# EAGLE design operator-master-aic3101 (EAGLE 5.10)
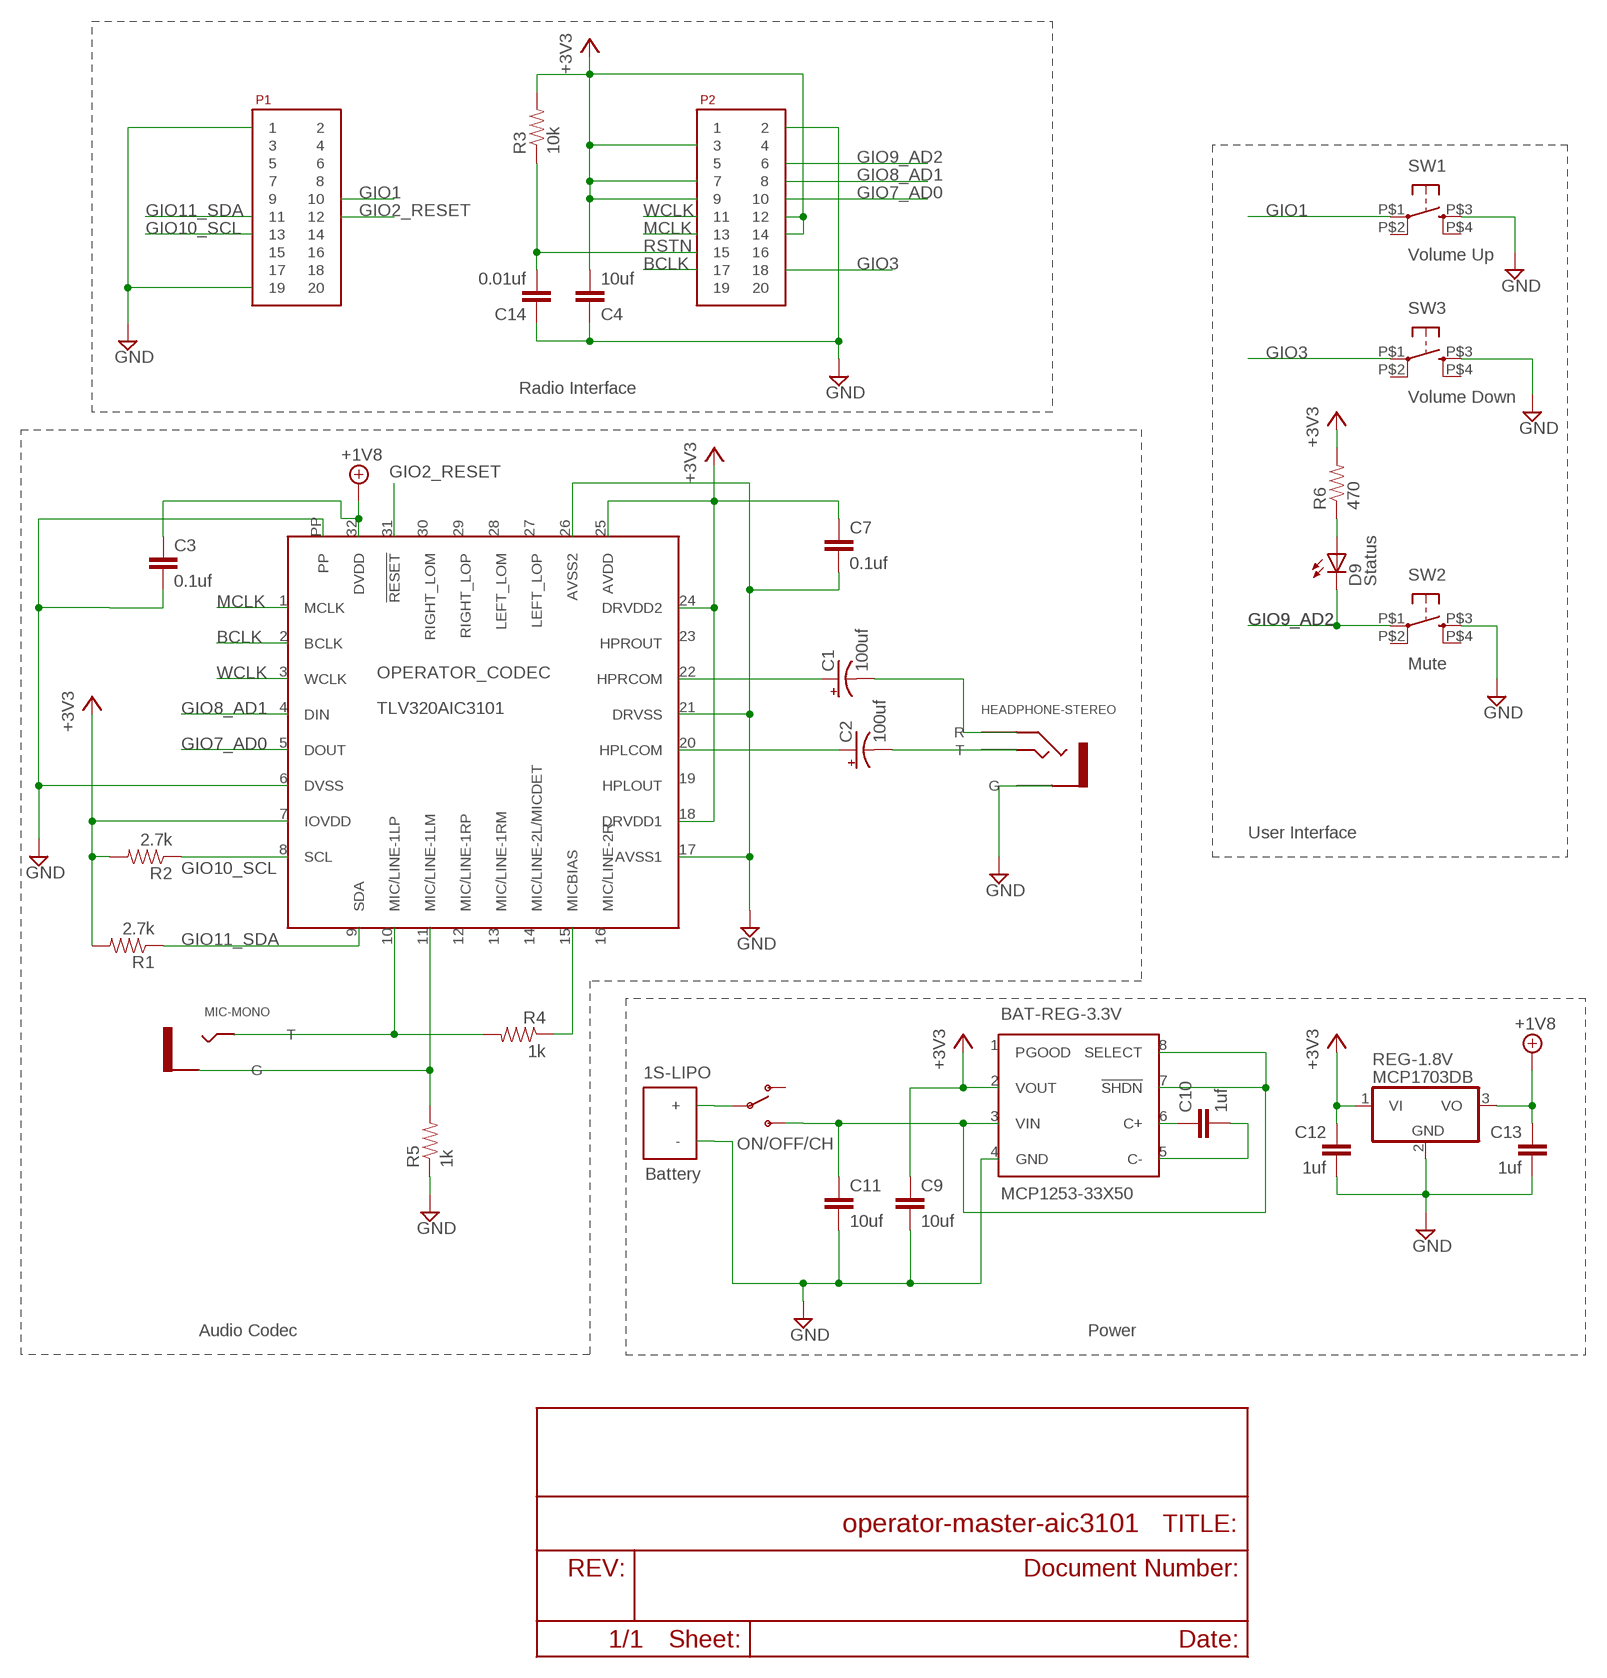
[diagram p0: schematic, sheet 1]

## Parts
1S-LIPO  Battery  JST-2MM-BAT-RIGHT-ANGLE  [JST-2MM-BAT-RIGHT-ANGLE]
BAT-REG-3.3V  MCP1253-33X50  [8MSOP]
C1  100uf  CPOL-USTT2D5  [TT2D5]
C2  100uf  CPOL-USTT2D5  [TT2D5]
C3  0.1uf  C-EUC1206  [C1206]
C4  10uf  C-EUC1206  [C1206]
C7  0.1uf  C-EUC1206  [C1206]
C9  10uf  C-EUC1206  [C1206]
C10  1uf  C-EUC1206  [C1206]
C11  10uf  C-EUC1206  [C1206]
C12  1uf  C-EUC1206  [C1206]
C13  1uf  C-EUC1206  [C1206]
C14  0.01uf  C-EUC1206  [C1206]
D9  Status  LEDCHIPLED_0805  [CHIPLED_0805]
HEADPHONE-STEREO  HEADPHONE-STEREO-NO-SWITCH  [HEADPHONE-STEREO-NO-SWITCH]
MIC-MONO  MIC-MONO  [MIC-MONO-SWITCH]
ON/OFF/CH  SWITCH-SPSTSMD2  [SWITCH-SPDT-SMD]
OPERATOR_CODEC  TLV320AIC3101  [SCHMARTBOARD-VQFN32-POWERPAD]
P1  SAMTEC-10X2  [SAMTEC-10X2]
P2  SAMTEC-10X2  [SAMTEC-10X2]
R1  2.7k  RESISTOR1206  [1206]
R2  2.7k  RESISTOR1206  [1206]
R3  10k  RESISTOR1206  [1206]
R4  1k  RESISTOR1206  [1206]
R5  1k  RESISTOR1206  [1206]
R6  470  RESISTOR1206  [1206]
REG-1.8V  MCP1703DB  [SOT223]
SW1  Volume Up  TAC_SWITCHKSA_SEALED  [KSA_SEALED_TAC_SWITCH]
SW2  Mute  TAC_SWITCHKSA_SEALED  [KSA_SEALED_TAC_SWITCH]
SW3  Volume Down  TAC_SWITCHKSA_SEALED  [KSA_SEALED_TAC_SWITCH]

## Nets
+3V3: BAT-REG-3.3V.2(VOUT) C4.2 C7.1 C9.1 C12.1 OPERATOR_CODEC.7(IOVDD) OPERATOR_CODEC.18(DRVDD1) OPERATOR_CODEC.24(DRVDD2) OPERATOR_CODEC.25(AVDD) P2.3 P2.7 P2.9 P2.12 P2.14 R1.2 R2.2 R3.2 R6.2 REG-1.8V.1(VI)
+18V: C3.1 C13.1 OPERATOR_CODEC.32(DVDD) REG-1.8V.3(VO) ; supply symbol labelled +1V8
BCLK: OPERATOR_CODEC.2(BCLK) P2.17
GIO1: P1.10 SW1.P$1
GIO2_RESET: OPERATOR_CODEC.31(!RESET) P1.12
GIO3: P2.18 SW3.P$1
GIO7_AD0: OPERATOR_CODEC.5(DOUT) P2.10
GIO8_AD1: OPERATOR_CODEC.4(DIN) P2.8
GIO9_AD2: D9.C P2.6 SW2.P$1
GIO10_SCL: OPERATOR_CODEC.8(SCL) P1.13 R2.1
GIO11_SDA: OPERATOR_CODEC.9(SDA) P1.11 R1.1
GND: 1S-LIPO.- BAT-REG-3.3V.4(GND) C3.2 C4.1 C7.2 C9.2 C11.2 C12.2 C13.2 C14.1 HEADPHONE-STEREO.G OPERATOR_CODEC.6(DVSS) OPERATOR_CODEC.17(AVSS1) OPERATOR_CODEC.21(DRVSS) OPERATOR_CODEC.26(AVSS2) OPERATOR_CODEC.PP P1.1 P1.19 P2.2 R5.1 REG-1.8V.2(GND) SW1.P$3 SW2.P$3 SW3.P$3
MCLK: OPERATOR_CODEC.1(MCLK) P2.13
N$1: MIC-MONO.G OPERATOR_CODEC.11(MIC/LINE-1LM) R5.2
N$2: 1S-LIPO.+ ON/OFF/CH.2(P)
N$3: MIC-MONO.T OPERATOR_CODEC.10(MIC/LINE-1LP) R4.2
N$4: OPERATOR_CODEC.15(MICBIAS) R4.1
N$5: C1.+ OPERATOR_CODEC.22(HPRCOM)
N$6: C2.+ OPERATOR_CODEC.20(HPLCOM)
N$7: C2.- HEADPHONE-STEREO.T
N$8: C1.- HEADPHONE-STEREO.R
N$10: D9.A R6.1
N$11: BAT-REG-3.3V.6(C+) C10.1
N$12: BAT-REG-3.3V.5(C-) C10.2
N$14: BAT-REG-3.3V.3(VIN) BAT-REG-3.3V.7(!SHDN) BAT-REG-3.3V.8(SELECT) C11.1 ON/OFF/CH.3(S)
RSTN: C14.2 P2.15 R3.1
WCLK: OPERATOR_CODEC.3(WCLK) P2.11
Unconnected: BAT-REG-3.3V.1(PGOOD) ON/OFF/CH.1(O) OPERATOR_CODEC.12(MIC/LINE-1RP) OPERATOR_CODEC.13(MIC/LINE-1RM) OPERATOR_CODEC.14(MIC/LINE-2L/MICDET) OPERATOR_CODEC.16(MIC/LINE-2R) OPERATOR_CODEC.19(HPLOUT) OPERATOR_CODEC.23(HPROUT) OPERATOR_CODEC.27(LEFT_LOP) OPERATOR_CODEC.28(LEFT_LOM) OPERATOR_CODEC.29(RIGHT_LOP) OPERATOR_CODEC.30(RIGHT_LOM) P1.2 P1.3 P1.4 P1.5 P1.6 P1.7 P1.8 P1.9 P1.14 P1.15 P1.16 P1.17 P1.18 P1.20 P2.1 P2.4 P2.5 P2.16 P2.19 P2.20 SW1.P$2 SW1.P$4 SW2.P$2 SW2.P$4 SW3.P$2 SW3.P$4

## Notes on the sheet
- Radio Interface
- User Interface
- Audio Codec | Power

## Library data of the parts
1S-LIPO = trl:JST-2MM-BAT-RIGHT-ANGLE
BAT-REG-3.3V = trl:MCP1253-33X50
C1 C2 = rcl:CPOL-US: POLARIZED CAPACITOR, American symbol
C3 C4 C7 C9-C14 = rcl:C-EU: CAPACITOR, European symbol
D9 = led:LED: LED
HEADPHONE-STEREO = trl:HEADPHONE-STEREO-NO-SWITCH
MIC-MONO = trl:MIC-MONO
ON/OFF/CH = SparkFun:SWITCH-SPST: SPST Switch Simple slide switch. Spark Fun Electronics SKU : COM-00102
OPERATOR_CODEC = trl:TLV320AIC3101
P1 P2 = trl:SAMTEC-10X2
R1-R6 = SparkFun:RESISTOR: Resistor
REG-1.8V = linear:MCP1703: 250 mA, 16V, Low Quiescent Current LDO Regulator Source: http://ww1.microchip.com/downloads/en/DeviceDoc/22049b.pdf
SW1-SW3 = SparkFun:TAC_SWITCH: Momentary Switch Button commonly used for reset or general input. Spark Fun Electronics SKU : COM-00097

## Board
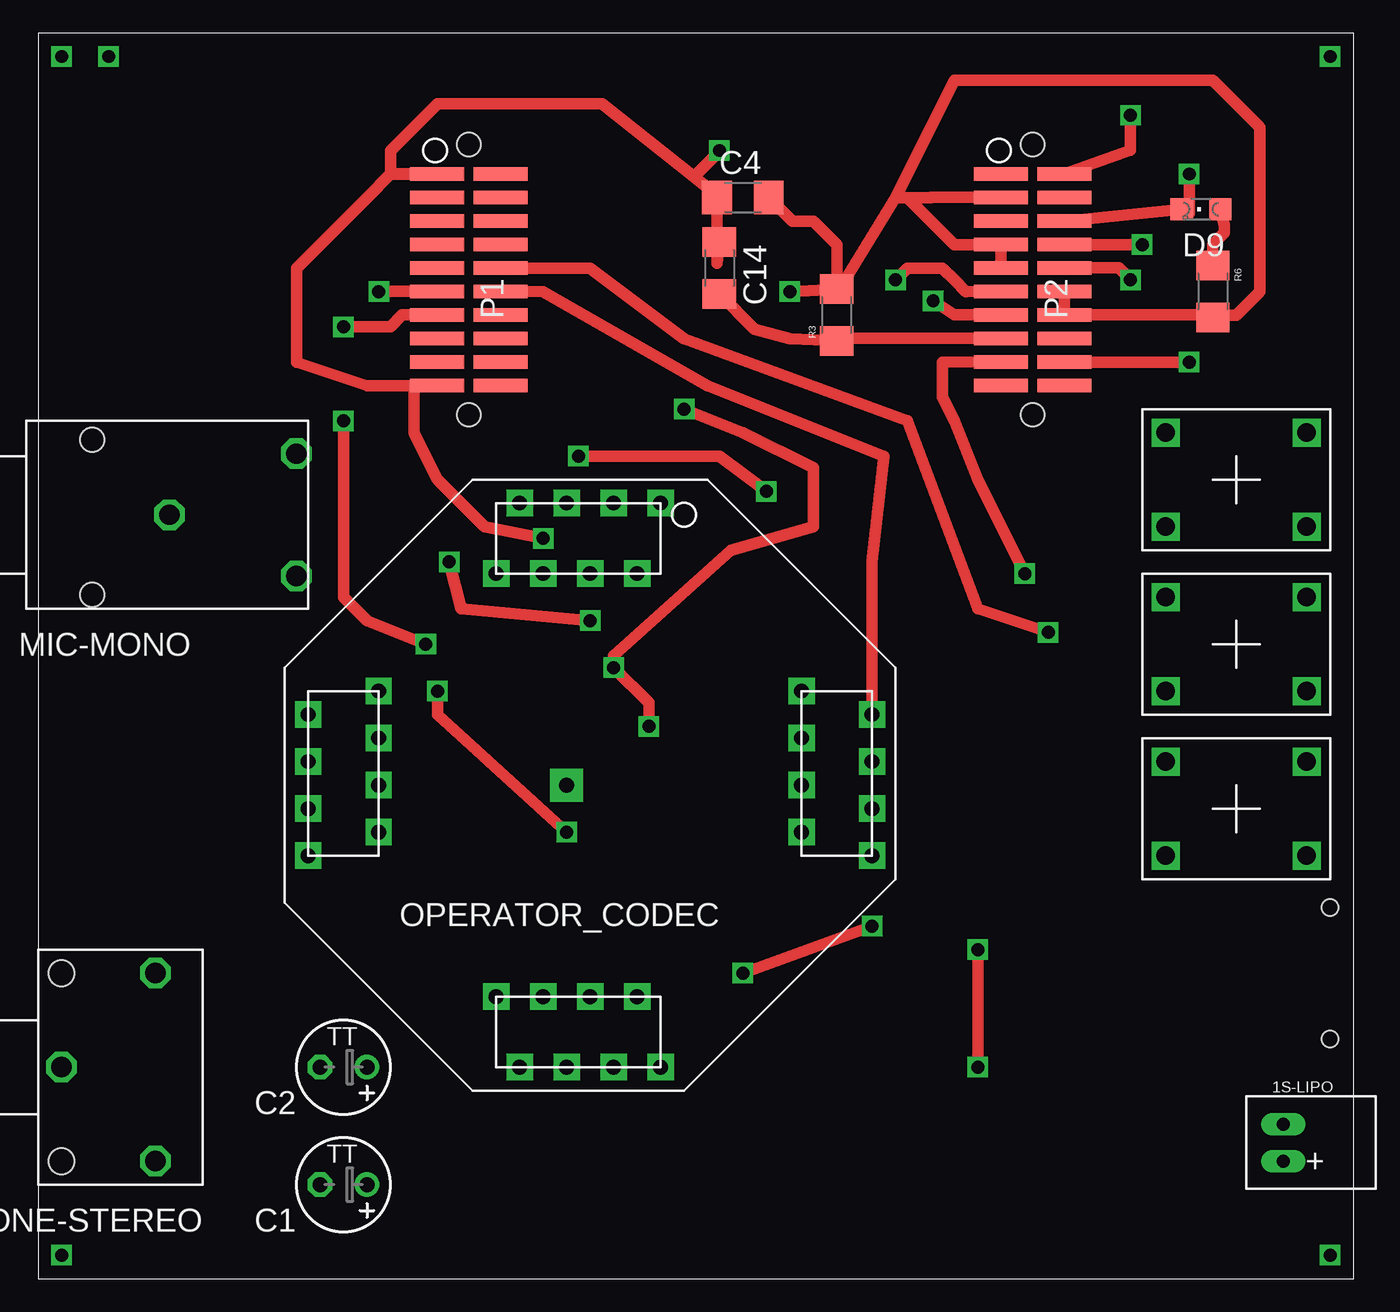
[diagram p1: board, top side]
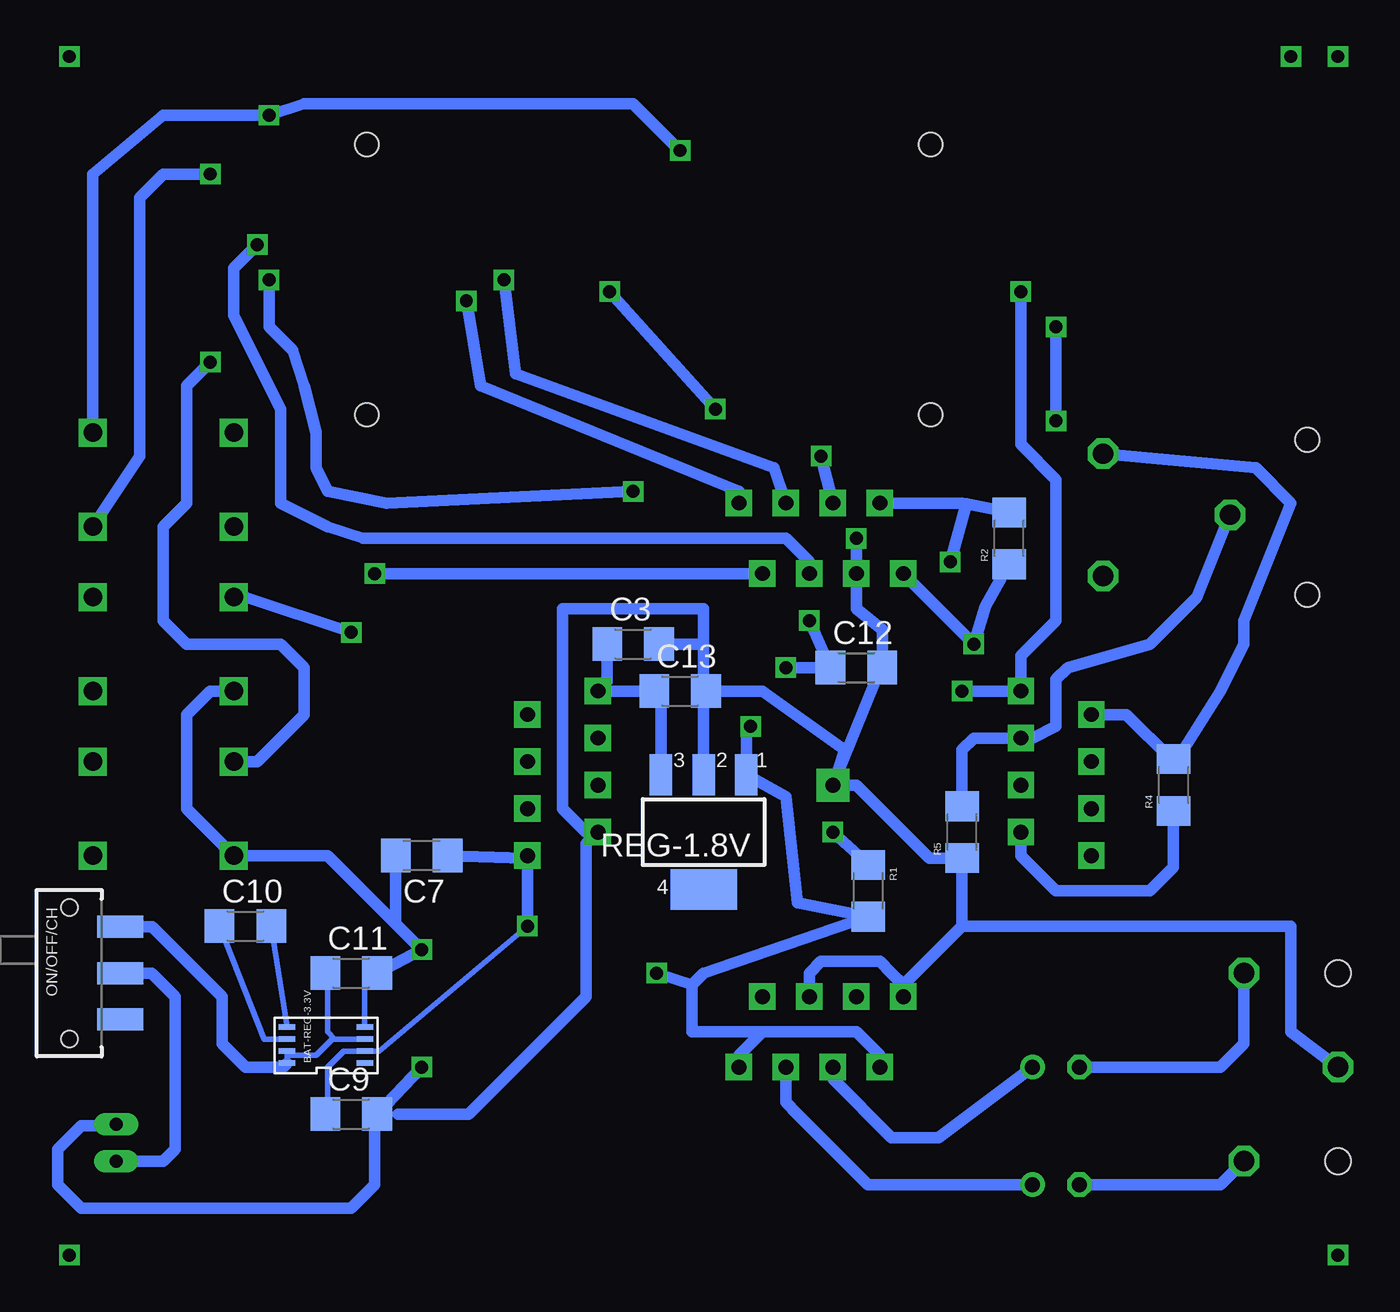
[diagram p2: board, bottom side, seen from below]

No outline drawn. Coordinates in mm, seen from the top.
Copper layers (1*16): Top 0.035mm / dielectric 1.5mm / Bottom 0.035mm
Design rules "default": minimum track width 10mil, minimum drill 24mil, track to track 8mil, track to pad 8mil, pad to pad 8mil, via to via 8mil, smd to smd 8mil, copper to edge 40mil, drill to drill 8mil, minimum pad ring 10mil, minimum via ring 8mil, stop-mask expansion 4mil, vias tented up to drill 0mil, thermal gap 10mil

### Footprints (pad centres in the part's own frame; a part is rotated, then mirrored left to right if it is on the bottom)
JST-2MM-BAT-RIGHT-ANGLE = drill 0.7 pad 1.016 long: + -2.54,-1.27; - -2.54,0.73
8MSOP = smd 0.3 x 0.9: 1 -1.05,-2; 2 -0.4,-2; 3 0.25,-2; 4 0.9,-2; 5 0.9,2.2; 6 0.25,2.2; 7 -0.4,2.2; 8 -1.05,2.2
TT2D5 = drill 0.813 round: + -1.27,0 | drill 0.813 octagon: - 1.27,0
C1206 = smd 1.6 x 1.8: 1 -1.4,0; 2 1.4,0
CHIPLED_0805 = smd 1.2 x 1.2: A 0,-1.05; C 0,1.05
HEADPHONE-STEREO-NO-SWITCH = drill 1.1 octagon: G 5.08,0; R 0,5.08; T 0,-5.08 | hole 1.4: 5.08,5.08; 5.08,-5.08
MIC-MONO-SWITCH = drill 1.1 octagon: G -2.667,-1.27; SW -9.525,2.032; T -9.525,-4.572 | hole 1.3: 1.524,3.048; 1.524,-5.334
SWITCH-SPDT-SMD = smd 1.2 x 2.5: 1 -2.5,-2.75; 2 0,-2.75; 3 2.5,-2.75 | hole 0.9: -3.55,0; 3.55,0
SCHMARTBOARD-VQFN32-POWERPAD = drill 0.8 pad 1.422 square: 1 -4.445,-15.24; 2 -3.175,-11.43; 3 -1.905,-15.24; 4 -0.635,-11.43; 5 0.635,-15.24; 6 1.905,-11.43; 7 3.175,-15.24; 8 4.445,-11.43; 9 10.795,-5.08; 10 14.605,-3.81; 11 10.795,-2.54; 12 14.605,-1.27; 13 10.795,0; 14 14.605,1.27; 15 10.795,2.54; 16 14.605,3.81; 17 4.445,11.43; 18 3.175,15.24; 19 1.905,11.43; 20 0.635,15.24; 21 -0.635,11.43; 22 -1.905,15.24; 23 -3.175,11.43; 24 -4.445,15.24; 25 -15.875,3.81; 26 -12.065,2.54; 27 -15.875,1.27; 28 -12.065,0; 29 -15.875,-1.27; 30 -12.065,-2.54; 31 -15.875,-3.81; 32 -12.065,-5.08 | drill 0.8 pad 1.778 square: PP 0.635,0
SAMTEC-10X2 = smd 0.74 x 2.92: 1 -6.358,-1.296; 2 -6.358,2.134; 3 -5.088,-1.296; 4 -5.088,2.134; 5 -3.818,-1.296; 6 -3.818,2.134; 7 -2.548,-1.296; 8 -2.548,2.134; 9 -1.278,-1.296; 10 -1.278,2.134; 11 -0.008,-1.296; 12 -0.008,2.134; 13 1.262,-1.296; 14 1.262,2.134; 15 2.532,-1.296; 16 2.532,2.134; 17 3.802,-1.296; 18 3.802,2.134; 19 5.072,-1.296; 20 5.072,2.134 | hole 1.27: -7.938,0.42; 6.66,0.42
1206 = smd 1.6 x 1.8: 1 -1.4,0; 2 1.4,0
SOT223 = smd 1.219 x 2.235: 1 -2.311,-3.099; 2 0,-3.099; 3 2.311,-3.099 | smd 3.6 x 2.2: 4 0,3.099
KSA_SEALED_TAC_SWITCH = drill 1 square: P$1 -3.81,2.54; P$2 3.81,2.54; P$3 -3.81,-2.54; P$4 3.81,-2.54

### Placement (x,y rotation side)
1S-LIPO  69.85,7.62 0 top
BAT-REG-3.3V  55.88,12.7 90 bottom
C1  16.51,5.08 180 top
C2  16.51,11.43 180 top
C3  39.37,34.29 0 bottom
C4  38.1,58.42 0 top
C7  50.8,22.86 180 bottom
C9  54.61,8.89 0 bottom
C10  60.33,19.05 0 bottom
C11  54.61,16.51 0 bottom
C12  27.3,33.02 0 bottom
C13  36.83,31.75 0 bottom
C14  36.83,54.61 270 top
D9  62.87,57.78 90 top
HEADPHONE-STEREO  6.35,11.43 180 top
MIC-MONO  4.45,40.01 180 top
ON/OFF/CH  69.85,16.51 90 bottom
OPERATOR_CODEC  29.21,26.67 180 top
P1  22.86,53.34 270 top
P2  53.34,53.34 270 top
R1  26.67,20.95 270 bottom
R2  19.05,40.01 90 bottom
R3  43.18,52.07 90 top
R4  10.16,26.67 90 bottom
R5  21.59,24.13 90 bottom
R6  63.5,53.34 270 top
REG-1.8V  35.56,24.13 180 bottom
SW1  64.77,34.29 0 top
SW2  64.77,43.18 180 top
SW3  64.77,25.4 0 top

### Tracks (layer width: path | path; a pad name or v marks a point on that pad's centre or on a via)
+3V3  (via drill 0.7)
  Top 0.61: P2.3 48.27,58.43 48.26,58.42 46.99,58.42 | 46.35,58.42 46.99,58.42 | 46.35,58.42 46.99,58.42 | 46.99,58.42 49.53,55.88 P2.7 P2.9 | P2.12 P2.14 63.36,52.08 R6.2 63.63,52.07 64.77,52.07 66.04,53.34 66.04,62.23 63.5,64.77 49.53,64.77 48.26,62.23 46.35,58.42 | R3.2 43.31,53.47 46.35,58.42 | R3.2 43.18,55.88 41.91,57.15 40.77,57.15 C4.2 | v33.02,29.84 33.02,31.11 v31.11,33.02 31.11,33.66 37.47,39.37 41.91,40.64 41.91,43.81 38.1,45.72 v34.92,46.99 | v40.64,53.34 R3.2 | v29.84,35.56 22.86,36.2 v22.23,38.73 | v38.1,16.51 v45.09,19.05
  Bottom 0.305: C9.1 55.88,9.02 55.88,11.43 55.01,12.3 BAT-REG-3.3V.2 53.1,12.3 v45.09,19.05 OPERATOR_CODEC.25
  Bottom 0.61: v33.02,29.84 33.25,29.62 REG-1.8V.1 31.11,26.04 30.48,20.32 R1.2 35.56,16.51 36.2,15.88 | v31.11,33.02 C12.1 v29.84,35.56 | OPERATOR_CODEC.7 22.86,41.91 21.59,41.91 21.35,41.86 | v34.92,46.99 v40.64,53.34 | 21.35,41.86 R2.2 | v22.23,38.73 21.35,41.86 | OPERATOR_CODEC.18 26.04,12.06 27.3,13.34 | 27.3,13.34 32.38,13.34 33.66,12.06 OPERATOR_CODEC.24 | 27.3,13.34 36.2,13.34 36.2,15.88 | v45.09,19.05 OPERATOR_CODEC.25 45.22,22.73 C7.1 | 36.2,15.88 v38.1,16.51
+18V
  Bottom 0.61: REG-1.8V.3 37.87,31.39 C13.1 OPERATOR_CODEC.32 40.77,32.26 C3.1
BCLK  (via drill 0.7)
  Top 0.61: v53.34,38.1 50.8,43.18 49.53,46.35 48.9,47.62 48.9,49.53 P2.17
  Bottom 0.61: OPERATOR_CODEC.2 v53.34,38.1
GIO1  (via drill 0.7)
  Top 0.61: v54.61,34.92 50.8,36.2 46.99,46.35 34.92,50.8 29.84,54.61 25,54.61 P1.10
  Bottom 0.61: SW1.P$1 60.33,36.83 v54.61,34.92
GIO2_RESET
  Top 0.61: OPERATOR_CODEC.31 45.09,34.29 45.09,38.73 45.72,44.45 36.2,48.26 27.3,53.34 P1.12
GIO3  (via drill 0.7)
  Top 0.61: v62.23,49.53 55.48,49.53 P2.18
  Bottom 0.61: SW3.P$1 59.69,27.94 57.15,30.48 57.15,33.02 58.42,34.29 63.5,34.29 64.77,35.56 64.77,40.64 63.5,41.91 63.5,48.26 v62.23,49.53
GIO7_AD0  (via drill 0.7)
  Top 0.61: P2.10 58.41,54.62 v59.05,53.98 | v39.37,42.55 36.83,44.45 v29.21,44.45
  Bottom 0.61: v59.05,53.98 59.05,52.07 59.05,51.44 57.78,50.16 57.15,48.26 56.52,45.72 56.52,43.81 55.88,42.55 52.7,41.91 v39.37,42.55 | OPERATOR_CODEC.5 v29.21,44.45
GIO8_AD1  (via drill 0.7)
  Top 0.61: v59.69,55.88 55.48,55.88 P2.8
  Bottom 0.61: OPERATOR_CODEC.4 29.84,38.73 31.11,40.01 53.98,40.01 55.88,40.64 58.42,41.91 58.42,46.99 60.96,52.07 60.96,54.61 v59.69,55.88
GIO9_AD2  (via drill 0.7)
  Top 0.61: P2.6 55.48,57.15 D9.C 62.23,57.56 v62.23,59.69
  Bottom 0.61: SW2.P$1 66.04,44.45 66.04,48.26 66.04,58.42 64.77,59.69 v62.23,59.69
GIO10_SCL  (via drill 0.7)
  Top 0.61: P1.13 19.69,52.08 19.05,51.44 v16.51,51.44 | v16.51,46.35 16.51,36.83 17.78,35.56 v20.95,34.29
  Bottom 0.61: v16.51,46.35 v16.51,51.44 | R2.1 20.32,36.33 v20.95,34.29 OPERATOR_CODEC.8
GIO11_SDA  (via drill 0.7)
  Top 0.61: v21.59,31.75 21.59,30.48 v28.57,24.13 | P1.11 18.42,53.35 v18.41,53.34
  Bottom 0.61: v21.59,31.75 OPERATOR_CODEC.9 18.41,33.66 16.51,35.56 16.51,43.18 18.41,45.09 v18.41,53.34 | v28.57,24.13 27.18,22.86 R1.1
GND  (via drill 0.7)
  Top 0.61: 35.45,59.55 30.48,63.5 26.67,63.5 | 35.45,59.55 36.7,58.55 C4.1 36.7,54.87 C14.1 | 26.67,63.5 27.94,63.5 26.67,63.5 | 26.67,63.5 21.59,63.5 20.32,62.23 19.05,60.96 19.05,59.69 P1.1 19.06,59.7 17.78,58.42 16.51,57.15 13.97,54.61 13.97,49.53 17.78,48.26 20.32,48.26 | 55.48,59.69 P2.2 59.05,60.97 v59.05,62.87 | v36.83,60.96 36.83,60.93 35.45,59.55 | 20.32,48.26 P1.19 | v27.3,40.01 24.13,40.64 22.86,41.91 21.59,43.18 20.95,44.45 20.32,45.72 20.32,48.26 | v50.8,11.43 v50.8,17.78
  Bottom 0.305: 52.07,8.89 C9.2 | C11.2 53.88,15.84 BAT-REG-3.3V.4 53.88,17.24
  Bottom 0.61: SW2.P$3 68.58,57.15 68.58,59.69 64.77,62.87 v59.05,62.87 57.15,63.5 54.61,63.5 39.37,63.5 v36.83,60.96 | SW1.P$3 62.23,31.75 63.5,30.48 63.5,25.4 SW3.P$3 55.88,22.86 v50.8,17.78 | OPERATOR_CODEC.PP 26.04,32.89 C12.2 25.91,35.05 27.3,36.2 OPERATOR_CODEC.6 v27.3,40.01 | C13.2 32.38,31.75 27.94,28.57 OPERATOR_CODEC.PP | 24.77,15.88 OPERATOR_CODEC.17 24.77,15.88 | 21.59,19.05 24.77,15.88 | 21.59,19.05 R5.1 23.36,22.73 24.77,24.13 27.3,26.67 OPERATOR_CODEC.PP | HEADPHONE-STEREO.G 3.81,13.34 3.81,19.05 21.59,19.05 | REG-1.8V.2 35.56,31.62 C13.2 | 35.56,34.29 35.56,33.66 35.56,31.88 C13.2 | 35.56,34.29 35.56,36.2 43.18,36.2 43.18,33.02 43.18,25.4 41.91,24.13 OPERATOR_CODEC.26 41.91,23.5 41.91,20.32 41.91,15.24 45.72,11.43 48.26,8.89 49.53,8.89 52.07,8.89 | 24.77,15.88 25.4,16.51 26.04,17.14 29.21,17.14 29.84,16.51 OPERATOR_CODEC.21 | 1S-LIPO.- 67.41,8.26 69.22,8.26 70.48,6.99 70.48,5.08 69.22,3.81 54.61,3.81 53.34,5.08 53.34,8.76 C9.2 v50.8,11.43 | v50.8,17.78 C11.2 | 35.56,34.29 C3.2 | C7.2 52.2,19.18 v50.8,17.78
MCLK  (via drill 0.7)
  Top 0.61: P2.13 49.52,52.08 v48.39,52.83
  Bottom 0.61: v48.39,52.83 47.62,48.26 33.66,42.55 OPERATOR_CODEC.1
N$1
  Bottom 0.61: MIC-MONO.G 8.89,36.83 11.43,34.29 15.88,33.02 16.51,32.38 16.51,29.84 17.78,29.21 OPERATOR_CODEC.11 20.95,29.21 21.59,28.57 R5.2
N$2
  Bottom 0.61: 1S-LIPO.+ 64.77,6.35 64.14,6.99 64.14,15.24 65.41,16.51 ON/OFF/CH.2
N$3
  Bottom 0.61: MIC-MONO.T 5.71,43.81 3.81,41.91 6.35,35.56 6.35,34.29 7.62,31.75 10.03,27.94 R4.2 10.29,28.07 12.7,30.48 OPERATOR_CODEC.10
N$4
  Bottom 0.61: R4.1 10.16,22.23 11.43,20.95 16.51,20.95 18.41,22.86 OPERATOR_CODEC.15
N$5
  Bottom 0.61: OPERATOR_CODEC.22 31.11,9.53 30.48,8.89 26.67,5.08 C1.+
N$6
  Bottom 0.61: OPERATOR_CODEC.20 28.57,10.79 25.4,7.62 22.86,7.62 C2.+
N$7
  Bottom 0.61: C2.- 7.62,11.43 6.35,12.7 HEADPHONE-STEREO.T
N$8
  Bottom 0.61: C1.- 7.62,5.08 HEADPHONE-STEREO.R
N$10
  Top 0.61: R6.1 63.5,55.88 64.14,56.52 64.14,56.93 D9.A
N$11
  Bottom 0.305: BAT-REG-3.3V.6 59.31,12.95 C10.1
N$12
  Bottom 0.305: BAT-REG-3.3V.5 C10.2
N$13  (via drill 0.7)
  other vias: 1.27,1.27 69.85,1.27 69.85,66.04 1.27,66.04 3.81,66.04
N$14
  Bottom 0.305: BAT-REG-3.3V.8 BAT-REG-3.3V.7 57.84,12.06 56.52,12.06 55.63,12.95 BAT-REG-3.3V.3 55.49,12.95 55.88,13.34 55.88,16.38 C11.1
  Bottom 0.61: ON/OFF/CH.3 65.36,19.01 61.59,15.24 61.59,12.7 60.33,11.43 58.3,11.43 BAT-REG-3.3V.8
RSTN
  Top 0.61: P2.15 43.32,50.81 R3.1 40.64,50.8 38.73,51.3 C14.2
WCLK  (via drill 0.7)
  Top 0.61: v46.35,53.98 46.99,54.61 48.9,54.61 49.53,53.98 50.16,53.34 P2.11
  Bottom 0.61: OPERATOR_CODEC.3 31.75,43.81 45.72,48.9 v46.35,53.98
